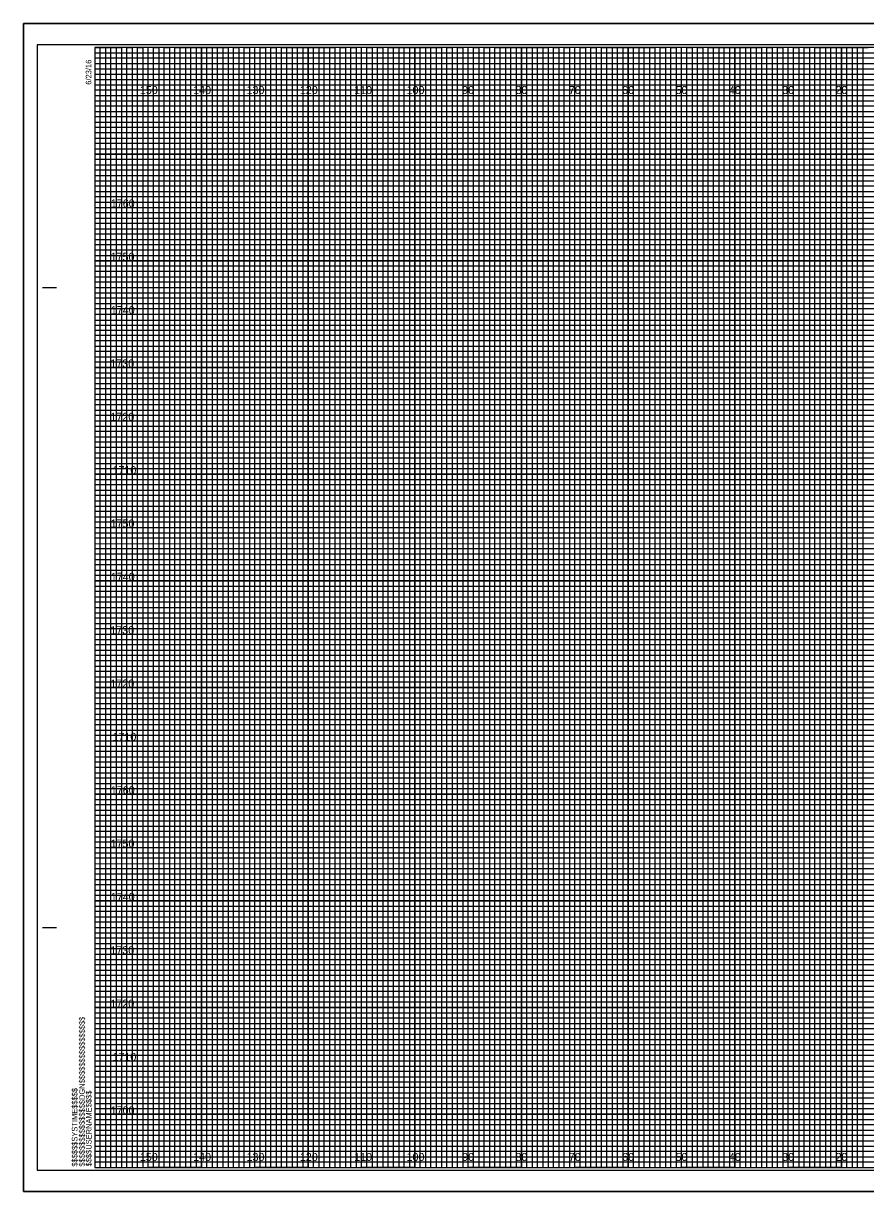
# Model space of a CAD drawing. Extents: x -419 to 4739, y -630 to 13534.
# Drawn here: x -13.4 to 144.5, y 1315.5 to 1534.5 of the extents above; entities that cross this region are included whole.
import ezdxf

# ---------------------------------------------------------------- set-up
doc = ezdxf.new("R2010")
doc.units = 0
for name, color, linetype in [('Old_Level_62', 7, 'Continuous'), ('Pattern 1', 7, 'Continuous'), ('Pattern 18', 7, 'Continuous'), ('Pattern 4', 7, 'Continuous'), ('Pattern 5', 7, 'Continuous'), ('Prop Dimension', 7, 'Continuous'), ('Prop Horizontal Alignment', 7, 'Continuous'), ('Raster_Level_0', 7, 'Continuous'), ('Scratch_Level_0', 7, 'Continuous'), ('Scratch_Level_3', 7, 'Continuous'), ('Scratch_Level_5', 7, 'Continuous')]:
    doc.layers.add(name, color=color, linetype=linetype)

msp = doc.modelspace()

# ---------------------------------------------------------------- linework, layer by layer
at = {"layer": 'Old_Level_62'}
for p, q in [((-9.8, 1485), (-7.3, 1485)), ((-9.7, 1485), (-7.2, 1485)), ((-9.8, 1365), (-7.3, 1365)), ((-9.7, 1365), (-7.2, 1365)), ((0, 1320), (0, 1320)), ((0, 1320), (0, 1320)), ((0, 1320), (0, 1320)), ((0, 1320), (0, 1320)), ((0, 1320), (0, 1320)), ((0, 1320), (0, 1320)), ((0, 1320), (0, 1320))]:
    msp.add_line(p, q, dxfattribs=at)
msp.add_lwpolyline([(320, 1530), (0, 1530), (0, 1320), (320, 1320)], close=True, dxfattribs=at)
at = {"layer": 'Pattern 18'}
for points in [[(-13.4, 1315.5), (323.3, 1315.5), (323.3, 1534.5), (-13.4, 1534.5)], [(-13.4, 1534.5), (323.3, 1534.5), (323.3, 1315.5), (-13.4, 1315.5)]]:
    msp.add_lwpolyline(points, close=True, dxfattribs=at)
at = {"layer": 'Pattern 4'}
for p, q in [((0, 1529), (260, 1529)), ((260, 1527.98), (0, 1527.98)), ((0, 1527.98), (0, 1527)), ((0, 1527), (260, 1527)), ((260, 1525.89), (0, 1525.89)), ((0, 1525.89), (0, 1524)), ((0, 1524), (320, 1524))]:
    msp.add_line(p, q, dxfattribs=at)
for points in [[(0, 1523), (270, 1523), (320, 1523), (320, 1522), (0, 1522)], [(0, 1521), (320, 1521), (320, 1519), (0, 1519)], [(0, 1518), (320, 1518), (320, 1517), (0, 1516.98)], [(0, 1516), (320, 1516), (320, 1514), (0, 1514)], [(0, 1513), (320, 1513), (320, 1512), (0, 1512)], [(0, 1511), (320, 1511), (320, 1509), (0, 1509)], [(0, 1508), (320, 1508), (320, 1507), (0, 1507)], [(0, 1506), (320, 1506), (320, 1504), (0, 1504)], [(0, 1503), (320, 1503), (320, 1502), (0, 1502)], [(0, 1501), (320, 1501), (320, 1499), (0, 1499)], [(0, 1498), (320, 1498), (320, 1497), (0, 1497)], [(0, 1496), (320, 1496), (320, 1493.95), (320, 1493), (320, 1492), (0, 1492)], [(0, 1494), (320, 1494), (320, 1493), (0, 1493)], [(0, 1491), (320, 1491), (320, 1489), (0, 1489.03)], [(0, 1489.03), (320, 1489), (320, 1488), (0, 1488)], [(0, 1487), (320, 1487), (320, 1486), (0, 1486)], [(0, 1484), (320, 1484), (320, 1483), (0, 1483)], [(0, 1482), (320, 1482), (320, 1481), (0, 1481)], [(-0.07, 1478.89), (320, 1478.89), (320, 1477.88), (-0.07, 1477.88)], [(0, 1477), (320, 1477), (320, 1476), (0, 1476)], [(0, 1474), (320, 1474), (320, 1473), (0, 1473)], [(0, 1472), (320, 1472), (320, 1471), (0, 1471)], [(0, 1469), (320, 1469), (320, 1468), (0, 1468)], [(0, 1467), (320, 1467), (320, 1466), (0, 1466)], [(0, 1464), (320, 1464), (320, 1463), (0, 1463)], [(0, 1462), (320, 1462), (320, 1461), (0, 1461)], [(0, 1459), (320, 1459), (319.99, 1457.98), (0, 1458)], [(0, 1457), (320, 1457), (320, 1456), (0, 1456)], [(0, 1454), (320, 1454), (320, 1453), (0, 1453)], [(0, 1452), (320, 1452), (320, 1451), (0, 1451)], [(0, 1449), (320, 1449), (320, 1448), (0, 1448)], [(0, 1447), (320, 1447), (320, 1446), (0, 1446)], [(0, 1444), (320, 1444), (320, 1443), (0, 1443)], [(0, 1442), (320, 1442), (320, 1441), (0, 1441)], [(0, 1439), (320, 1439), (320, 1438), (0, 1438)], [(0, 1436.99), (320.07, 1436.91), (320, 1436), (0, 1436)], [(0, 1434), (320, 1434), (320, 1433), (0, 1433)], [(0, 1432), (320, 1432), (320, 1431), (0, 1431)], [(0, 1429), (320, 1429), (320, 1428), (0, 1428)], [(0, 1427), (320, 1427), (320, 1426), (0, 1426)], [(0, 1424), (320, 1424), (320, 1423), (0, 1423)], [(0, 1422), (320, 1422), (320, 1421), (0, 1421)], [(0, 1419), (320, 1419), (320, 1418), (0, 1418)], [(0, 1417), (320, 1417), (320, 1416), (0, 1416)], [(0, 1414), (320, 1414), (320, 1413), (0, 1413)], [(0, 1412), (320, 1412), (320, 1411), (0, 1411)], [(0, 1409), (320, 1409), (320, 1408), (0, 1408)], [(0, 1407), (320, 1407), (320, 1406), (0, 1406)], [(0, 1404), (320, 1404), (320, 1403), (0, 1403)], [(0, 1402), (320, 1402), (320, 1401), (0, 1401)], [(0, 1399), (320, 1399), (319.99, 1397.98), (0, 1398)], [(0, 1397), (320, 1397), (320, 1396), (0, 1396)], [(0, 1394), (320, 1394), (320, 1393), (0, 1393)], [(0, 1392), (320, 1392), (320, 1391), (0, 1391)], [(0, 1389), (320, 1389), (320, 1388), (0, 1388)], [(0, 1387), (320, 1387), (320, 1386), (0, 1386)], [(0, 1384), (320, 1384), (320, 1383), (0, 1383)], [(0, 1382), (320, 1382), (320, 1381), (0, 1381)], [(0, 1379), (320, 1379), (320, 1378), (0, 1378)], [(0, 1376.99), (320.07, 1376.91), (320, 1376), (0, 1376)], [(0, 1374), (320, 1374), (320, 1373), (0, 1373)], [(0, 1372), (320, 1372), (320, 1371), (0, 1371)], [(0, 1369), (320, 1369), (320, 1368), (0, 1368)], [(0, 1367), (320, 1367), (320, 1366), (0, 1366)], [(0, 1364), (320, 1364), (320, 1363), (0, 1363)], [(0, 1362), (320, 1362), (320, 1361), (0, 1361)], [(0, 1359), (320, 1359), (320, 1358), (0, 1358)], [(0, 1357), (320, 1357), (320, 1356), (0, 1356)], [(0, 1354), (320, 1354), (320, 1353), (0, 1353)], [(0, 1352), (320, 1352), (320, 1351), (0, 1351)], [(0, 1349), (320, 1349), (320, 1348), (0, 1348)], [(0, 1347), (320, 1347), (320, 1346), (0, 1346)], [(0, 1344), (320, 1344), (320, 1343), (0, 1343)], [(0, 1342), (320, 1342), (320, 1341), (0, 1341)], [(0, 1339), (320, 1339), (320, 1338), (0, 1338)], [(0, 1337), (320, 1337), (320, 1336), (0, 1336)], [(0, 1334), (320, 1334), (320, 1333), (0, 1333)], [(0, 1332), (320, 1332), (320, 1331), (0, 1331)], [(0, 1329), (320, 1329), (320, 1328), (0, 1328)], [(0, 1327), (320, 1327), (320, 1326), (0, 1326)], [(0, 1324), (320, 1324), (320, 1323), (0, 1323)], [(0, 1322), (320, 1322), (320, 1321), (0, 1321)]]:
    msp.add_lwpolyline(points, dxfattribs=at)
at = {"layer": 'Pattern 5'}
for p, q in [((323.3, 1534.5), (-13.4, 1534.5)), ((-13.4, 1534.5), (-13.4, 1315.5)), ((-13.4, 1315.5), (323.3, 1315.5))]:
    msp.add_line(p, q, dxfattribs=at)
at = {"layer": 'Prop Dimension'}
for points in [[(0, 1320), (1, 1320), (1, 1530), (2, 1530), (2, 1320)], [(2, 1320), (3, 1320), (3, 1530), (4, 1530), (4, 1320)], [(5, 1320), (6, 1320), (6, 1530), (7, 1530), (7, 1320)], [(7, 1320), (8, 1320), (8, 1530), (9, 1530), (9, 1320)], [(10, 1320), (11, 1320), (11, 1530), (12, 1530), (12, 1320)], [(12, 1320), (13, 1320), (13, 1530), (14, 1530), (14, 1320)], [(15, 1320), (16, 1320), (16, 1530), (17, 1530), (17, 1320)], [(17, 1320), (18, 1320), (18, 1530), (19, 1530), (19, 1320)], [(20, 1320), (21, 1320), (21, 1530), (22, 1530), (22, 1320)], [(22, 1320), (23, 1320), (23, 1530), (24, 1530), (24, 1320)], [(25, 1320), (26, 1320), (26, 1530), (27, 1530), (27, 1320)], [(27, 1320), (28, 1320), (28, 1530), (29, 1530), (29, 1320)], [(30, 1320), (31, 1320), (31, 1530), (32, 1530), (32, 1320)], [(32, 1320), (33, 1320), (33, 1530), (34, 1530), (34, 1320)], [(35, 1320), (36, 1320), (36, 1530), (37, 1530), (37, 1320)], [(37, 1320), (38, 1320), (38, 1530), (39, 1530), (39, 1320)], [(40, 1320), (41, 1320), (41, 1530), (42, 1530), (42, 1320)], [(42, 1320), (43, 1320), (43, 1530), (44, 1530), (44, 1320)], [(45, 1320), (46, 1320), (46, 1530), (47, 1530), (47, 1320)], [(47, 1320), (48, 1320), (48, 1530), (49, 1530), (49, 1320)], [(50, 1320), (51, 1320), (51, 1530), (52, 1530), (52, 1320)], [(52, 1320), (53, 1320), (53, 1530), (54, 1530), (54, 1320)], [(55, 1320), (56, 1320), (56, 1530), (57, 1530), (57, 1320)], [(57, 1320), (58, 1320), (58, 1530), (59, 1530), (59, 1320)], [(60, 1320), (61, 1320), (61, 1530), (62, 1530), (62, 1320)], [(62, 1320), (63, 1320), (63, 1530), (64, 1530), (64, 1320)], [(65, 1320), (66, 1320), (66, 1530), (67, 1530), (67, 1320)], [(67, 1320), (68, 1320), (68, 1530), (69, 1530), (69, 1320)], [(70, 1320), (71, 1320), (71, 1530), (72, 1530), (72, 1320)], [(72, 1320), (73, 1320), (73, 1530), (74, 1530), (74, 1320)], [(75, 1320), (76, 1320), (76, 1530), (77, 1530), (77, 1320)], [(77, 1320), (78, 1320), (78, 1530), (79, 1530), (79, 1320)], [(80, 1320), (81, 1320), (81, 1530), (82, 1530), (82, 1320)], [(82, 1320), (83, 1320), (83, 1530), (84, 1530), (84, 1320)], [(85, 1320), (86, 1320), (86, 1530), (87, 1530), (87, 1320)], [(87, 1320), (88, 1320), (88, 1530), (89, 1530), (89, 1320)], [(90, 1320), (91, 1320), (91, 1530), (92, 1530), (92, 1320)], [(92, 1320), (93, 1320), (93, 1530), (94, 1530), (94, 1320)], [(95, 1320), (96, 1320), (96, 1530), (97, 1530), (97, 1320)], [(97, 1320), (98, 1320), (98, 1530), (99, 1530), (99, 1320)], [(100, 1320), (101, 1320), (101, 1530), (102, 1530), (102, 1320)], [(102, 1320), (103, 1320), (103, 1530), (104, 1530), (104, 1320)], [(105, 1320), (106, 1320), (106, 1530), (107, 1530), (107, 1320)], [(107, 1320), (108, 1320), (108, 1530), (109, 1530), (109, 1320)], [(110, 1320), (111, 1320), (111, 1530), (112, 1530), (112, 1320)], [(112, 1320), (113, 1320), (113, 1530), (114, 1530), (114, 1320)], [(115, 1320), (116, 1320), (116, 1530), (117, 1530), (117, 1320)], [(117, 1320), (118, 1320), (118, 1530), (119, 1530), (119, 1320)], [(120, 1320), (121, 1320), (121, 1530), (122, 1530), (122, 1320)], [(122, 1320), (123, 1320), (123, 1530), (124, 1530), (124, 1320)], [(125, 1320), (126, 1320), (126, 1530), (127, 1530), (127, 1320)], [(127, 1320), (128, 1320), (128, 1530), (129, 1530), (129, 1320)], [(130, 1320), (131, 1320), (131, 1530), (132, 1530), (132, 1320)], [(132, 1320), (133, 1320), (133, 1530), (134, 1530), (134, 1320)], [(135, 1320), (136, 1320), (136, 1530), (137, 1530), (137, 1320)], [(137, 1320), (138, 1320), (138, 1530), (139, 1530), (139, 1320)], [(140, 1320), (141, 1320), (141, 1530), (142, 1530), (142, 1320)], [(142, 1320), (143, 1320), (143, 1530), (144, 1530), (144, 1320)]]:
    msp.add_lwpolyline(points, dxfattribs=at)
at = {"layer": 'Prop Horizontal Alignment'}
for points in [[(0, 1530), (5, 1530), (5, 1320), (15, 1320), (15, 1530), (25, 1530), (25, 1320), (35, 1320), (35, 1530), (45, 1530), (45, 1320), (55, 1320), (55, 1530), (65, 1530), (65, 1320), (75, 1320), (75, 1530), (85, 1530), (85, 1320), (95, 1320), (95, 1530), (105, 1530), (105, 1320), (115, 1320), (115, 1530), (125, 1530), (125, 1320), (135, 1320), (135, 1530), (145, 1530)], [(0, 1525), (275, 1525)], [(0, 1505), (320, 1505), (320, 1515), (0, 1515)], [(0, 1485), (320, 1485), (320, 1495), (0, 1495)], [(0, 1465), (320, 1465), (320, 1475), (0, 1475)], [(0, 1445), (320, 1445), (320, 1455), (0, 1455)], [(0, 1425), (320, 1425), (320, 1435), (0, 1435)], [(0, 1405), (320, 1405), (320, 1415), (0, 1415)], [(0, 1385), (320, 1385), (320, 1395), (0, 1395)], [(0, 1365), (320, 1365), (320, 1375), (0, 1375)], [(0, 1345), (320, 1345), (320, 1355), (0, 1355)], [(0, 1325), (320, 1325), (320, 1335), (0, 1335)]]:
    msp.add_lwpolyline(points, dxfattribs=at)
at = {"layer": 'Scratch_Level_0'}
for p, q in [((10, 1320), (10, 1530)), ((20, 1320), (20, 1530)), ((30, 1320), (30, 1530)), ((40, 1320), (40, 1530)), ((50, 1320), (50, 1530)), ((60, 1320), (60, 1530)), ((70, 1320), (70, 1530)), ((80, 1320), (80, 1530)), ((90, 1320), (90, 1530)), ((100, 1320), (100, 1530)), ((110, 1320), (110, 1530)), ((120, 1320), (120, 1530)), ((130, 1320), (130, 1530)), ((140, 1320), (140, 1530)), ((0, 1520), (320, 1520)), ((0, 1510), (320, 1510)), ((0, 1500), (320, 1500)), ((0, 1490), (320, 1490)), ((0, 1480), (320, 1480)), ((0, 1470), (320, 1470)), ((0, 1460), (320, 1460)), ((0, 1450), (320, 1450)), ((0, 1440), (320, 1440)), ((0, 1430), (320, 1430)), ((0, 1420), (320, 1420)), ((0, 1410), (320, 1410)), ((0, 1400), (320, 1400)), ((0, 1390), (320, 1390)), ((0, 1380), (320, 1380)), ((0, 1370), (320, 1370)), ((0, 1360), (320, 1360)), ((0, 1350), (320, 1350)), ((0, 1340), (320, 1340)), ((0, 1330), (320, 1330))]:
    msp.add_line(p, q, dxfattribs=at)
at = {"layer": 'Scratch_Level_3'}
for p, q in [((10, 1530), (0, 1530)), ((10, 1320), (10, 1530)), ((30, 1530), (20, 1530)), ((20, 1530), (20, 1320)), ((30, 1320), (30, 1530)), ((50, 1530), (40, 1530)), ((40, 1530), (40, 1320)), ((50, 1320), (50, 1530)), ((70, 1530), (60, 1530)), ((60, 1530), (60, 1320)), ((70, 1320), (70, 1530)), ((90, 1530), (80, 1530)), ((80, 1530), (80, 1320)), ((90, 1320), (90, 1530)), ((110, 1530), (100, 1530)), ((100, 1530), (100, 1320)), ((110, 1320), (110, 1530)), ((130, 1530), (120, 1530)), ((120, 1530), (120, 1320)), ((130, 1320), (130, 1530)), ((150, 1530), (140, 1530)), ((140, 1530), (140, 1320)), ((20, 1320), (10, 1320)), ((40, 1320), (30, 1320)), ((60, 1320), (50, 1320)), ((80, 1320), (70, 1320)), ((100, 1320), (90, 1320)), ((120, 1320), (110, 1320)), ((140, 1320), (130, 1320))]:
    msp.add_line(p, q, dxfattribs=at)
for points in [[(0, 1520), (320, 1520), (320, 1510), (0, 1510)], [(0, 1500), (320, 1500), (320, 1490), (0, 1490)], [(0, 1480), (320, 1480), (320, 1470), (0, 1470)], [(0, 1460), (320, 1460), (320, 1450), (0, 1450)], [(0, 1440), (320, 1440), (320, 1430), (0, 1430)], [(0, 1420), (320, 1420), (320, 1410), (0, 1410)], [(0, 1400), (320, 1400), (320, 1390), (0, 1390)], [(0, 1380), (320, 1380), (320, 1370), (0, 1370)], [(0, 1360), (320, 1360), (320, 1350), (0, 1350)], [(0, 1340), (320, 1340), (320, 1330), (0, 1330)]]:
    msp.add_lwpolyline(points, dxfattribs=at)
at = {"layer": 'Scratch_Level_5'}
msp.add_lwpolyline([(-10.8, 1319.5), (322.4, 1319.5), (322.4, 1530.5), (-10.8, 1530.5)], close=True, dxfattribs=at)

# ---------------------------------------------------------------- texts
at = {"layer": 'Old_Level_62'}
for s, p in [('6/23/16', (-0.65, 1523)), ('$$$$$$$$$$$$$$$$DGN$$$$$$$$$$$$$$$$', (-1.88, 1320.18)), ('$$$$$$SYSTIME$$$$$', (-3.26, 1320.18)), ('$$$$USERNAME$$$$', (-0.62, 1320.23))]:
    msp.add_text(s, height=1.05, rotation=90, dxfattribs=at).set_placement(p)
at = {"layer": 'Pattern 1'}
for s, p in [('1760', (3, 1500)), ('1750', (2.96, 1490)), ('1740', (3, 1480)), ('1730', (2.92, 1470)), ('1720', (2.93, 1460)), ('1710', (3.31, 1450)), ('1750', (2.96, 1440)), ('1740', (3, 1430)), ('1730', (2.92, 1420)), ('1720', (2.93, 1410)), ('1710', (3.31, 1400)), ('1760', (3, 1390)), ('1750', (2.96, 1380)), ('1740', (3, 1370)), ('1730', (2.92, 1360)), ('1720', (2.93, 1350)), ('1710', (3.31, 1340)), ('1700', (2.98, 1330))]:
    msp.add_text(s, height=1.5, dxfattribs=at).set_placement(p)
at = {"layer": 'Raster_Level_0'}
for s, p in [('150', (8.44, 1521.25)), ('140', (18.44, 1521.25)), ('130', (28.44, 1521.25)), ('120', (38.44, 1521.25)), ('110', (48.62, 1521.25)), ('100', (58.44, 1521.25)), ('90', (68.86, 1521.25)), ('80', (78.86, 1521.25)), ('70', (88.86, 1521.25)), ('60', (98.86, 1521.25)), ('50', (108.86, 1521.25)), ('40', (118.86, 1521.25)), ('30', (128.86, 1521.25)), ('20', (138.86, 1521.25)), ('150', (8.44, 1321.25)), ('140', (18.44, 1321.25)), ('130', (28.44, 1321.25)), ('120', (38.44, 1321.25)), ('110', (48.62, 1321.25)), ('100', (58.44, 1321.25)), ('90', (68.86, 1321.25)), ('80', (78.86, 1321.25)), ('70', (88.86, 1321.25)), ('60', (98.86, 1321.25)), ('50', (108.86, 1321.25)), ('40', (118.86, 1321.25)), ('30', (128.86, 1321.25)), ('20', (138.86, 1321.25))]:
    msp.add_text(s, height=1.5, dxfattribs=at).set_placement(p)

doc.saveas('drawing.dxf')
